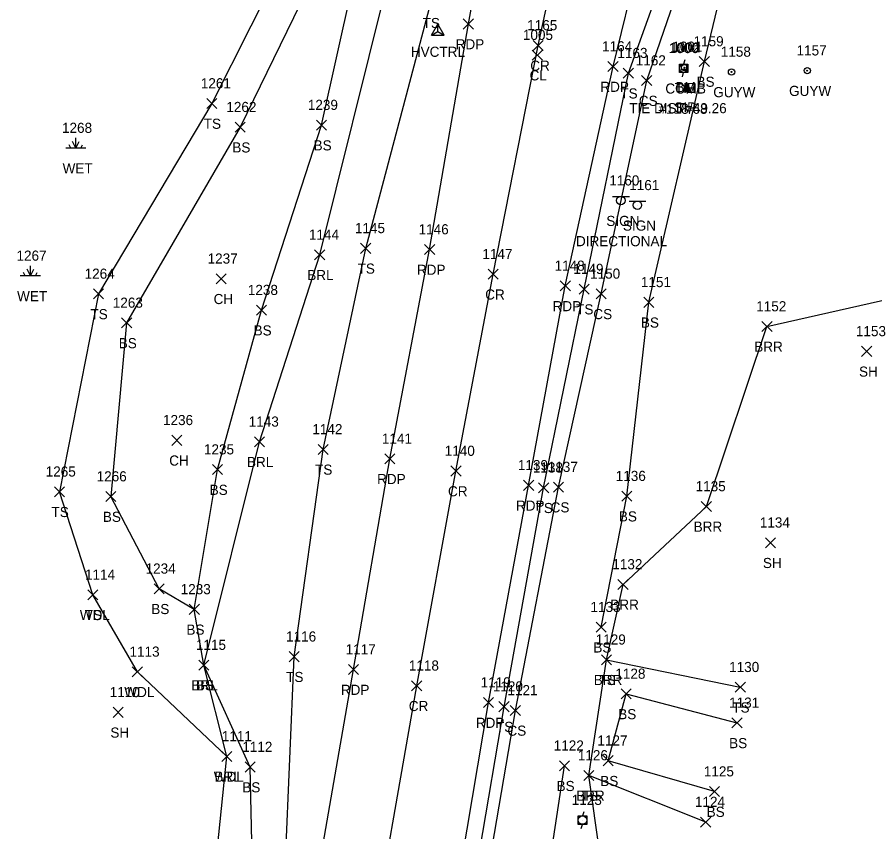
# Model space of a CAD drawing. Extents: x 1654425 to 1656893, y 667839 to 678429.
# Drawn here: x 1654474.9 to 1654644.4, y 668104.4 to 668265.4 of the extents above; entities that cross this region are included whole.
import ezdxf

# ---------------------------------------------------------------- set-up
doc = ezdxf.new("R2010")
doc.units = 0
for name, color, linetype in [('A_A', 7, 'Continuous'), ('A_I', 7, 'Continuous'), ('A_TIC', 7, 'Continuous'), ('C_A', 7, 'Continuous'), ('C_C', 7, 'Continuous'), ('C_I', 7, 'Continuous'), ('CBP', 7, 'Continuous'), ('CPBM', 7, 'Continuous'), ('CPSM', 7, 'Continuous'), ('L_A', 7, 'Continuous'), ('L_I', 7, 'Continuous'), ('L_TIC', 7, 'Continuous'), ('LABL', 7, 'Continuous'), ('LAWA', 7, 'Continuous'), ('LELB', 7, 'Continuous'), ('LWET', 7, 'Continuous'), ('P_A', 7, 'Continuous'), ('P_I', 7, 'Continuous'), ('P_TIC', 7, 'Continuous'), ('PET', 7, 'Continuous'), ('PRC', 7, 'Continuous'), ('S_A', 7, 'Continuous'), ('S_C', 7, 'Continuous'), ('S_I', 7, 'Continuous'), ('SSGN', 7, 'Continuous'), ('U_A', 7, 'Continuous'), ('U_C', 7, 'Continuous'), ('U_I', 7, 'Continuous'), ('UP', 7, 'Continuous'), ('UPGW', 7, 'Continuous')]:
    doc.layers.add(name, color=color, linetype=linetype)

msp = doc.modelspace()

# ---------------------------------------------------------------- linework, layer by layer
at = {"layer": 'A_TIC'}
for points in [[(1654576.68, 668256.91), (1654578.68, 668258.91)], [(1654578.68, 668256.91), (1654576.68, 668258.91)]]:
    msp.add_lwpolyline(points, dxfattribs=at)
at = {"layer": 'CBP'}
for radius in [0.625, 0.0833]:
    msp.add_circle((1654606.76, 668255.43), radius, dxfattribs=at)
at = {"layer": 'CPBM'}
for p, q in [((1654606.14, 668255.08), (1654606.14, 668256.08)), ((1654606.14, 668256.08), (1654607.14, 668256.08)), ((1654607.14, 668255.08), (1654606.14, 668255.08)), ((1654606.64, 668255.58), (1654606.64, 668255.58)), ((1654606.64, 668255.58), (1654606.64, 668255.58)), ((1654607.14, 668256.08), (1654607.14, 668255.08))]:
    msp.add_line(p, q, dxfattribs=at)
at = {"layer": 'CPSM'}
for p, q in [((1654556.76, 668261.85), (1654558.01, 668264.01)), ((1654559.26, 668261.85), (1654558.01, 668264.01)), ((1654558.01, 668262.57), (1654558.01, 668264.01)), ((1654556.76, 668261.85), (1654558.01, 668262.57)), ((1654556.76, 668261.85), (1654559.26, 668261.85)), ((1654558.01, 668262.57), (1654558.01, 668262.57)), ((1654558.01, 668262.57), (1654559.26, 668261.85))]:
    msp.add_line(p, q, dxfattribs=at)
at = {"layer": 'L_TIC'}
for points in [[(1654609.68, 668255.65), (1654611.68, 668257.65)], [(1654611.68, 668255.65), (1654609.68, 668257.65)], [(1654594.67, 668253.34), (1654596.67, 668255.34)], [(1654596.67, 668253.34), (1654594.67, 668255.34)], [(1654598.29, 668251.88), (1654600.29, 668253.88)], [(1654600.29, 668251.88), (1654598.29, 668253.88)], [(1654512.38, 668247.35), (1654514.38, 668249.35)], [(1654514.38, 668247.35), (1654512.38, 668249.35)], [(1654517.99, 668242.67), (1654519.99, 668244.67)], [(1654519.99, 668242.67), (1654517.99, 668244.67)], [(1654534.05, 668243.08), (1654536.05, 668245.08)], [(1654536.05, 668243.08), (1654534.05, 668245.08)], [(1654533.69, 668217.45), (1654535.69, 668219.45)], [(1654535.69, 668217.45), (1654533.69, 668219.45)], [(1654542.78, 668218.73), (1654544.78, 668220.73)], [(1654544.78, 668218.73), (1654542.78, 668220.73)], [(1654514.25, 668212.72), (1654516.25, 668214.72)], [(1654516.25, 668212.72), (1654514.25, 668214.72)], [(1654585.94, 668210.68), (1654587.94, 668212.68)], [(1654587.94, 668210.68), (1654585.94, 668212.68)], [(1654490, 668209.73), (1654492, 668211.73)], [(1654492, 668209.73), (1654490, 668211.73)], [(1654589.31, 668209.74), (1654591.31, 668211.74)], [(1654591.31, 668209.74), (1654589.31, 668211.74)], [(1654598.7, 668208.07), (1654600.7, 668210.07)], [(1654600.7, 668208.07), (1654598.7, 668210.07)], [(1654522.2, 668206.52), (1654524.2, 668208.52)], [(1654524.2, 668206.52), (1654522.2, 668208.52)], [(1654495.56, 668204), (1654497.56, 668206)], [(1654497.56, 668204), (1654495.56, 668206)], [(1654622.05, 668203.29), (1654624.05, 668205.29)], [(1654624.05, 668203.29), (1654622.05, 668205.29)], [(1654641.74, 668198.38), (1654643.74, 668200.38)], [(1654643.74, 668198.38), (1654641.74, 668200.38)], [(1654505.49, 668180.81), (1654507.49, 668182.81)], [(1654507.49, 668180.81), (1654505.49, 668182.81)], [(1654521.79, 668180.51), (1654523.79, 668182.51)], [(1654523.79, 668180.51), (1654521.79, 668182.51)], [(1654534.37, 668179.01), (1654536.37, 668181.01)], [(1654536.37, 668179.01), (1654534.37, 668181.01)], [(1654513.52, 668175.02), (1654515.52, 668177.02)], [(1654515.52, 668175.02), (1654513.52, 668177.02)], [(1654577.93, 668171.43), (1654579.93, 668173.43)], [(1654579.93, 668171.43), (1654577.93, 668173.43)], [(1654580.87, 668171.56), (1654582.87, 668173.56)], [(1654582.87, 668171.56), (1654580.87, 668173.56)], [(1654482.31, 668170.64), (1654484.31, 668172.64)], [(1654484.31, 668170.64), (1654482.31, 668172.64)], [(1654482.31, 668170.64), (1654484.31, 668172.64)], [(1654484.31, 668170.64), (1654482.31, 668172.64)], [(1654492.42, 668169.69), (1654494.42, 668171.69)], [(1654494.42, 668169.69), (1654492.42, 668171.69)], [(1654492.42, 668169.69), (1654494.42, 668171.69)], [(1654494.42, 668169.69), (1654492.42, 668171.69)], [(1654594.35, 668169.77), (1654596.35, 668171.77)], [(1654596.35, 668169.77), (1654594.35, 668171.77)], [(1654610.07, 668167.74), (1654612.07, 668169.74)], [(1654612.07, 668167.74), (1654610.07, 668169.74)], [(1654622.76, 668160.57), (1654624.76, 668162.57)], [(1654624.76, 668160.57), (1654622.76, 668162.57)], [(1654501.99, 668151.47), (1654503.99, 668153.47)], [(1654503.99, 668151.47), (1654501.99, 668153.47)], [(1654593.61, 668152.33), (1654595.61, 668154.33)], [(1654595.61, 668152.33), (1654593.61, 668154.33)], [(1654488.89, 668150.28), (1654490.89, 668152.28)], [(1654490.89, 668150.28), (1654488.89, 668152.28)], [(1654488.89, 668150.28), (1654490.89, 668152.28)], [(1654490.89, 668150.28), (1654488.89, 668152.28)], [(1654508.93, 668147.4), (1654510.93, 668149.4)], [(1654510.93, 668147.4), (1654508.93, 668149.4)], [(1654508.93, 668147.4), (1654510.93, 668149.4)], [(1654510.93, 668147.4), (1654508.93, 668149.4)], [(1654589.31, 668143.88), (1654591.31, 668145.88)], [(1654591.31, 668143.88), (1654589.31, 668145.88)], [(1654528.66, 668138.05), (1654530.66, 668140.05)], [(1654530.66, 668138.05), (1654528.66, 668140.05)], [(1654510.8, 668136.4), (1654512.8, 668138.4)], [(1654512.8, 668136.4), (1654510.8, 668138.4)], [(1654510.8, 668136.4), (1654512.8, 668138.4)], [(1654512.8, 668136.4), (1654510.8, 668138.4)], [(1654590.34, 668137.45), (1654592.34, 668139.45)], [(1654592.34, 668137.45), (1654590.34, 668139.45)], [(1654590.34, 668137.45), (1654592.34, 668139.45)], [(1654592.34, 668137.45), (1654590.34, 668139.45)], [(1654497.68, 668135.06), (1654499.68, 668137.06)], [(1654499.68, 668135.06), (1654497.68, 668137.06)], [(1654594.22, 668130.7), (1654596.22, 668132.7)], [(1654596.22, 668130.7), (1654594.22, 668132.7)], [(1654616.78, 668132.02), (1654618.78, 668134.02)], [(1654618.78, 668132.02), (1654616.78, 668134.02)], [(1654570.11, 668128.18), (1654572.11, 668130.18)], [(1654572.11, 668128.18), (1654570.11, 668130.18)], [(1654572.34, 668127.44), (1654574.34, 668129.44)], [(1654574.34, 668127.44), (1654572.34, 668129.44)], [(1654493.87, 668127.06), (1654495.87, 668129.06)], [(1654495.87, 668127.06), (1654493.87, 668129.06)], [(1654616.12, 668124.98), (1654618.12, 668126.98)], [(1654618.12, 668124.98), (1654616.12, 668126.98)], [(1654515.35, 668118.35), (1654517.35, 668120.35)], [(1654517.35, 668118.35), (1654515.35, 668120.35)], [(1654515.35, 668118.35), (1654517.35, 668120.35)], [(1654517.35, 668118.35), (1654515.35, 668120.35)], [(1654590.68, 668117.5), (1654592.68, 668119.5)], [(1654592.68, 668117.5), (1654590.68, 668119.5)], [(1654519.96, 668116.25), (1654521.96, 668118.25)], [(1654521.96, 668116.25), (1654519.96, 668118.25)], [(1654582.04, 668116.51), (1654584.04, 668118.51)], [(1654584.04, 668116.51), (1654582.04, 668118.51)], [(1654586.86, 668114.59), (1654588.86, 668116.59)], [(1654588.86, 668114.59), (1654586.86, 668116.59)], [(1654586.86, 668114.59), (1654588.86, 668116.59)], [(1654588.86, 668114.59), (1654586.86, 668116.59)], [(1654611.69, 668111.4), (1654613.69, 668113.4)], [(1654613.69, 668111.4), (1654611.69, 668113.4)], [(1654609.94, 668105.38), (1654611.94, 668107.38)], [(1654611.94, 668105.38), (1654609.94, 668107.38)]]:
    msp.add_lwpolyline(points, dxfattribs=at)
at = {"layer": 'LABL'}
for points in [[(1654516.35, 668119.35), (1654511.8, 668137.4), (1654522.79, 668181.51), (1654534.69, 668218.45), (1654547.69, 668270.66), (1654546.04, 668295.57)], [(1654605, 668046.16), (1654594.45, 668068.9), (1654587.86, 668115.59), (1654591.34, 668138.45), (1654594.61, 668153.33), (1654611.07, 668168.74), (1654623.05, 668204.29), (1654669.38, 668214.79), (1654714.24, 668210.79)]]:
    msp.add_lwpolyline(points, dxfattribs=at)
at = {"layer": 'LAWA'}
msp.add_lwpolyline([(1654487.86, 667850.24), (1654494.84, 667897.34), (1654500.67, 667940.77), (1654505.51, 667978.89), (1654509.61, 668019.56), (1654510.39, 668046.1), (1654508.8, 668074.55), (1654512.45, 668081.46), (1654516.35, 668119.35), (1654498.68, 668136.06), (1654489.89, 668151.28)], dxfattribs=at)
at = {"layer": 'LELB'}
for points in [[(1654562.65, 668358.71), (1654556.85, 668347.4), (1654550.86, 668336.48), (1654541.59, 668302.56), (1654534.79, 668276.13), (1654518.99, 668243.67), (1654496.56, 668205), (1654493.42, 668170.69)], [(1654495.43, 667849.08), (1654500.81, 667895.96), (1654505.52, 667939.5), (1654510.36, 667978.52), (1654516.04, 668017.45), (1654520.13, 668047.02), (1654521.8, 668078.81), (1654520.96, 668117.25), (1654511.8, 668137.4), (1654509.93, 668148.4), (1654514.52, 668176.02), (1654523.2, 668207.52), (1654535.05, 668244.08), (1654541.09, 668271.34), (1654546.04, 668295.57), (1654553.44, 668325.52), (1654559.28, 668346.56), (1654565.49, 668358.45)], [(1654497.51, 667848.84), (1654501.99, 667895.85), (1654506.8, 667938.86), (1654511.52, 667978.38), (1654518.04, 668017.75), (1654522.23, 668046.7), (1654527.11, 668078.6), (1654529.66, 668139.05), (1654535.37, 668180.01), (1654543.78, 668219.73), (1654556.62, 668268.25), (1654562.63, 668297.63), (1654565.24, 668311.03), (1654570.38, 668336.59), (1654576.33, 668345.51)], [(1654532.88, 667846.44), (1654536.81, 667893.31), (1654541.08, 667931.05), (1654546.18, 667972.49), (1654551.95, 668011.91), (1654556.54, 668041.44), (1654561.5, 668072.5), (1654571.11, 668129.18), (1654578.93, 668172.43), (1654586.94, 668211.68), (1654595.67, 668254.34), (1654607.41, 668286.92), (1654610.93, 668292.61), (1654617.54, 668318.12), (1654616.79, 668336.32)], [(1654590.31, 668144.88), (1654595.35, 668170.77), (1654599.7, 668209.07), (1654610.68, 668256.65), (1654619.6, 668293.68), (1654624.42, 668321.72), (1654620.94, 668333.17)], [(1654537.5, 668307.15), (1654528.81, 668278.95), (1654513.38, 668248.35), (1654491, 668210.73), (1654483.31, 668171.64)], [(1654543.76, 667929.96), (1654549.41, 667971.89), (1654554.38, 668011.7), (1654559.28, 668041.03), (1654563.69, 668071.7), (1654573.34, 668128.44), (1654581.87, 668172.56), (1654590.31, 668210.74), (1654599.29, 668252.88), (1654609.98, 668283.91), (1654610.93, 668292.61)], [(1654489.89, 668151.28), (1654483.31, 668171.64)], [(1654509.93, 668148.4), (1654502.99, 668152.47), (1654493.42, 668170.69)], [(1654591.34, 668138.45), (1654617.78, 668133.02)], [(1654612.69, 668112.4), (1654591.68, 668118.5), (1654595.22, 668131.7), (1654617.12, 668125.98)], [(1654538.26, 667846.15), (1654542.65, 667893.12), (1654546.8, 667929.18), (1654553.5, 667971.67), (1654558.51, 668011.64), (1654562.47, 668041.03), (1654569.65, 668073.66), (1654578.54, 668087.47), (1654583.04, 668117.51)], [(1654610.94, 668106.38), (1654587.86, 668115.59)]]:
    msp.add_lwpolyline(points, dxfattribs=at)
at = {"layer": 'LWET'}
for p, q in [((1654486.53, 668239.54), (1654486.53, 668241.54)), ((1654488.53, 668239.54), (1654484.53, 668239.54)), ((1654485.53, 668239.54), (1654485.2, 668240.21)), ((1654486.53, 668239.54), (1654485.86, 668240.87)), ((1654486.53, 668239.54), (1654487.2, 668240.87)), ((1654487.53, 668239.54), (1654487.86, 668240.21)), ((1654477.54, 668214.29), (1654477.54, 668216.29)), ((1654479.54, 668214.29), (1654475.54, 668214.29)), ((1654476.54, 668214.29), (1654476.21, 668214.96)), ((1654477.54, 668214.29), (1654476.88, 668215.62)), ((1654477.54, 668214.29), (1654478.21, 668215.62)), ((1654478.54, 668214.29), (1654478.88, 668214.96))]:
    msp.add_line(p, q, dxfattribs=at)
at = {"layer": 'P_TIC'}
for points in [[(1654563.06, 668263.06), (1654565.06, 668265.06)], [(1654565.06, 668263.06), (1654563.06, 668265.06)], [(1654576.86, 668258.83), (1654578.86, 668260.83)], [(1654578.86, 668258.83), (1654576.86, 668260.83)], [(1654591.64, 668254.65), (1654593.64, 668256.65)], [(1654593.64, 668254.65), (1654591.64, 668256.65)], [(1654555.41, 668218.5), (1654557.41, 668220.5)], [(1654557.41, 668218.5), (1654555.41, 668220.5)], [(1654567.95, 668213.62), (1654569.95, 668215.62)], [(1654569.95, 668213.62), (1654567.95, 668215.62)], [(1654582.21, 668211.31), (1654584.21, 668213.31)], [(1654584.21, 668211.31), (1654582.21, 668213.31)], [(1654547.54, 668177.15), (1654549.54, 668179.15)], [(1654549.54, 668177.15), (1654547.54, 668179.15)], [(1654560.61, 668174.74), (1654562.61, 668176.74)], [(1654562.61, 668174.74), (1654560.61, 668176.74)], [(1654574.97, 668171.91), (1654576.97, 668173.91)], [(1654576.97, 668171.91), (1654574.97, 668173.91)], [(1654540.38, 668135.51), (1654542.38, 668137.51)], [(1654542.38, 668135.51), (1654540.38, 668137.51)], [(1654552.86, 668132.31), (1654554.86, 668134.31)], [(1654554.86, 668132.31), (1654552.86, 668134.31)], [(1654567.05, 668128.99), (1654569.05, 668130.99)], [(1654569.05, 668128.99), (1654567.05, 668130.99)]]:
    msp.add_lwpolyline(points, dxfattribs=at)
at = {"layer": 'PET'}
for points in [[(1654500.93, 667848.14), (1654504.78, 667896.02), (1654509.67, 667937.82), (1654515.37, 667977.68), (1654521.39, 668016.85), (1654525.99, 668046.3), (1654531.26, 668078.24), (1654541.38, 668136.51), (1654548.54, 668178.15), (1654556.41, 668219.5), (1654564.06, 668264.06), (1654572.07, 668308.08), (1654579.91, 668345.23), (1654595.42, 668341.51), (1654611.88, 668337.75)], [(1654528.99, 667846.47), (1654531.96, 667893.38), (1654537.26, 667931.97), (1654542.41, 667973.09), (1654548.22, 668012.23), (1654553.01, 668041.79), (1654558.55, 668073.69), (1654568.05, 668129.99), (1654575.97, 668172.91), (1654583.21, 668212.31), (1654592.64, 668255.65), (1654604.22, 668302.74), (1654611.88, 668337.75)]]:
    msp.add_lwpolyline(points, dxfattribs=at)
at = {"layer": 'PRC'}
msp.add_lwpolyline([(1654514.39, 667847.42), (1654517.73, 667895.01), (1654522.68, 667935.26), (1654527.79, 667975.85), (1654533.53, 668014.87), (1654538.36, 668044.09), (1654543.94, 668076.54), (1654553.86, 668133.31), (1654561.61, 668175.74), (1654568.95, 668214.62), (1654577.86, 668259.83), (1654587.68, 668305.21), (1654595.42, 668341.51)], dxfattribs=at)
at = {"layer": 'SSGN'}
for p, q in [((1654592.52, 668230), (1654595.86, 668230)), ((1654594.17, 668229.17), (1654594.17, 668229.17)), ((1654595.81, 668229.08), (1654599.14, 668229.08)), ((1654597.45, 668228.25), (1654597.45, 668228.25))]:
    msp.add_line(p, q, dxfattribs=at)
for centre in [(1654594.17, 668229.17), (1654597.45, 668228.25)]:
    msp.add_circle(centre, 0.833, dxfattribs=at)
at = {"layer": 'UP'}
for p, q in [((1654606.84, 668256.98), (1654606.59, 668256.15)), ((1654605.75, 668254.48), (1654605.75, 668256.15)), ((1654605.75, 668256.15), (1654607.42, 668256.15)), ((1654606.59, 668255.31), (1654606.59, 668255.31)), ((1654607.42, 668256.15), (1654607.42, 668254.48)), ((1654607.42, 668254.48), (1654605.75, 668254.48)), ((1654606.34, 668253.65), (1654606.59, 668254.48)), ((1654585.78, 668105.93), (1654585.78, 668107.6)), ((1654585.78, 668107.6), (1654587.44, 668107.6)), ((1654586.86, 668108.43), (1654586.61, 668107.6)), ((1654587.44, 668107.6), (1654587.44, 668105.93)), ((1654587.44, 668105.93), (1654585.78, 668105.93)), ((1654586.36, 668105.1), (1654586.61, 668105.93)), ((1654586.61, 668106.77), (1654586.61, 668106.77))]:
    msp.add_line(p, q, dxfattribs=at)
for centre in [(1654606.59, 668255.31), (1654586.61, 668106.77)]:
    msp.add_circle(centre, 0.833, dxfattribs=at)
at = {"layer": 'UPGW'}
for centre, radius in [((1654616.05, 668254.59), 0.625), ((1654631.01, 668254.84), 0.625), ((1654631.01, 668254.84), 0.0833), ((1654616.05, 668254.59), 0.0833)]:
    msp.add_circle(centre, radius, dxfattribs=at)

# ---------------------------------------------------------------- texts
at = {"layer": 'A_A'}
msp.add_text('CL', height=2, dxfattribs=at).set_placement((1654576.16, 668252.91))
at = {"layer": 'A_I'}
msp.add_text('1005', height=2, dxfattribs=at).set_placement((1654574.83, 668260.91))
at = {"layer": 'C_A'}
for s, p in [('HVCTRL', (1654552.7, 668257.57)), ('TIE', (1654604.84, 668250.43)), ('BM', (1654604.96, 668250.58))]:
    msp.add_text(s, height=2, dxfattribs=at).set_placement(p)
at = {"layer": 'C_C'}
for s, p in [('TIE DIST=49.26', (1654595.84, 668246.43)), ('SIP', (1654604.74, 668246.58))]:
    msp.add_text(s, height=2, dxfattribs=at).set_placement(p)
at = {"layer": 'C_I'}
for s, p in [('1002', (1654603.91, 668258.43)), ('1001', (1654604.36, 668258.58))]:
    msp.add_text(s, height=2, dxfattribs=at).set_placement(p)
at = {"layer": 'L_A'}
for s, p in [('TS', (1654555.03, 668263.25)), ('BS', (1654609.12, 668251.65)), ('TS', (1654594.08, 668249.34)), ('CS', (1654597.73, 668247.88)), ('TS', (1654511.79, 668243.35)), ('BS', (1654517.44, 668238.67)), ('BS', (1654533.49, 668239.08)), ('WET', (1654483.91, 668234.54)), ('TS', (1654542.18, 668214.73)), ('BRL', (1654532.24, 668213.45)), ('WET', (1654474.92, 668209.29)), ('CH', (1654513.74, 668208.72)), ('TS', (1654489.41, 668205.73)), ('TS', (1654585.35, 668206.68)), ('CS', (1654588.75, 668205.74)), ('BS', (1654598.14, 668204.07)), ('BS', (1654521.64, 668202.52)), ('BS', (1654495, 668200)), ('BRR', (1654620.53, 668199.29)), ('SH', (1654641.23, 668194.38)), ('CH', (1654504.97, 668176.81)), ('BRL', (1654520.33, 668176.51)), ('TS', (1654533.78, 668175.01)), ('BS', (1654512.96, 668171.02)), ('TS', (1654481.72, 668166.64)), ('TS', (1654481.72, 668166.64)), ('TS', (1654577.34, 668167.43)), ('CS', (1654580.31, 668167.56)), ('BS', (1654491.86, 668165.69)), ('BS', (1654491.86, 668165.69)), ('BS', (1654593.79, 668165.77)), ('BRR', (1654608.56, 668163.74)), ('SH', (1654622.24, 668156.57)), ('BRR', (1654592.1, 668148.33)), ('WDL', (1654487.31, 668146.28)), ('TS', (1654488.3, 668146.28)), ('BS', (1654501.43, 668147.47)), ('BS', (1654508.37, 668143.4)), ('BS', (1654508.37, 668143.4)), ('BS', (1654588.75, 668139.88)), ('BRL', (1654509.34, 668132.4)), ('BS', (1654510.24, 668132.4)), ('TS', (1654528.07, 668134.05)), ('BRR', (1654588.83, 668133.45)), ('TS', (1654589.75, 668133.45)), ('WDL', (1654496.1, 668131.06)), ('TS', (1654616.19, 668128.02)), ('BS', (1654593.66, 668126.7)), ('TS', (1654569.52, 668124.18)), ('SH', (1654493.35, 668123.06)), ('CS', (1654571.78, 668123.44)), ('BS', (1654615.57, 668120.98)), ('WDL', (1654513.77, 668114.35)), ('BRL', (1654513.9, 668114.35)), ('BS', (1654519.4, 668112.25)), ('BS', (1654581.48, 668112.51)), ('BS', (1654590.12, 668113.5)), ('BRR', (1654585.35, 668110.59)), ('TS', (1654586.27, 668110.59)), ('BS', (1654611.13, 668107.4))]:
    msp.add_text(s, height=2, dxfattribs=at).set_placement(p)
at = {"layer": 'L_I'}
for s, p in [('1159', (1654608.54, 668259.65)), ('1163', (1654593.5, 668257.34)), ('1162', (1654597.12, 668255.88)), ('1261', (1654511.21, 668251.35)), ('1262', (1654516.25, 668246.67)), ('1239', (1654532.35, 668247.08)), ('1268', (1654483.79, 668242.54)), ('1145', (1654541.65, 668222.73)), ('1144', (1654532.57, 668221.45)), ('1267', (1654474.8, 668217.29)), ('1237', (1654512.55, 668216.72)), ('1264', (1654488.26, 668213.73)), ('1149', (1654584.81, 668214.68)), ('1150', (1654588.1, 668213.74)), ('1151', (1654598.14, 668212.07)), ('1238', (1654520.5, 668210.52)), ('1263', (1654493.82, 668208)), ('1152', (1654620.92, 668207.29)), ('1153', (1654640.61, 668202.38)), ('1236', (1654503.74, 668184.81)), ('1143', (1654520.67, 668184.51)), ('1142', (1654533.24, 668183.01)), ('1235', (1654511.83, 668179.02)), ('1138', (1654576.8, 668175.43)), ('1137', (1654579.74, 668175.56)), ('1265', (1654480.57, 668174.64)), ('1265', (1654480.57, 668174.64)), ('1266', (1654490.63, 668173.69)), ('1266', (1654490.63, 668173.69)), ('1136', (1654593.17, 668173.77)), ('1135', (1654608.95, 668171.74)), ('1134', (1654621.63, 668164.57)), ('1132', (1654592.49, 668156.33)), ('1234', (1654500.3, 668155.47)), ('1114', (1654488.33, 668154.28)), ('1114', (1654488.33, 668154.28)), ('1233', (1654507.23, 668151.4)), ('1233', (1654507.23, 668151.4)), ('1133', (1654588.18, 668147.88)), ('1116', (1654528.05, 668142.05)), ('1129', (1654589.21, 668141.45)), ('1129', (1654589.21, 668141.45)), ('1115', (1654510.24, 668140.4)), ('1115', (1654510.24, 668140.4)), ('1113', (1654497.12, 668139.06)), ('1130', (1654615.57, 668136.02)), ('1128', (1654593.09, 668134.7)), ('1110', (1654493.22, 668131.06)), ('1120', (1654568.89, 668132.18)), ('1121', (1654571.78, 668131.44)), ('1131', (1654615.57, 668128.98)), ('1111', (1654515.36, 668122.35)), ('1111', (1654515.36, 668122.35)), ('1122', (1654580.92, 668120.51)), ('1127', (1654589.55, 668121.5)), ('1112', (1654519.4, 668120.25)), ('1126', (1654585.68, 668118.59)), ('1126', (1654585.68, 668118.59)), ('1125', (1654610.57, 668115.4)), ('1124', (1654608.81, 668109.38))]:
    msp.add_text(s, height=2, dxfattribs=at).set_placement(p)
at = {"layer": 'P_A'}
for s, p in [('RDP', (1654561.55, 668259.06)), ('CR', (1654576.29, 668254.83)), ('RDP', (1654590.13, 668250.65)), ('RDP', (1654553.9, 668214.5)), ('CR', (1654567.39, 668209.62)), ('RDP', (1654580.7, 668207.31)), ('RDP', (1654546.03, 668173.15)), ('CR', (1654560.04, 668170.74)), ('RDP', (1654573.46, 668167.91)), ('RDP', (1654538.87, 668131.51)), ('CR', (1654552.29, 668128.31)), ('RDP', (1654565.53, 668124.99))]:
    msp.add_text(s, height=2, dxfattribs=at).set_placement(p)
at = {"layer": 'P_I'}
for s, p in [('1165', (1654575.68, 668262.83)), ('1164', (1654590.47, 668258.65)), ('1146', (1654554.23, 668222.5)), ('1147', (1654566.83, 668217.62)), ('1148', (1654581.09, 668215.31)), ('1141', (1654546.98, 668181.15)), ('1140', (1654559.39, 668178.74)), ('1139', (1654573.84, 668175.91)), ('1117', (1654539.82, 668139.51)), ('1118', (1654552.3, 668136.31)), ('1119', (1654566.48, 668132.99))]:
    msp.add_text(s, height=2, dxfattribs=at).set_placement(p)
at = {"layer": 'S_A'}
for p in [(1654591.31, 668224.15), (1654594.59, 668223.23)]:
    msp.add_text('SIGN', height=2, dxfattribs=at).set_placement(p)
at = {"layer": 'S_C'}
msp.add_text('DIRECTIONAL', height=2, dxfattribs=at).set_placement((1654585.32, 668220.15))
at = {"layer": 'S_I'}
for s, p in [('1160', (1654591.89, 668232.15)), ('1161', (1654595.83, 668231.23))]:
    msp.add_text(s, height=2, dxfattribs=at).set_placement(p)
at = {"layer": 'U_A'}
for s, p in [('COMB', (1654602.97, 668250.31)), ('GUYW', (1654612.44, 668249.59)), ('GUYW', (1654627.41, 668249.84))]:
    msp.add_text(s, height=2, dxfattribs=at).set_placement(p)
at = {"layer": 'U_C'}
msp.add_text('#118/68', height=2, dxfattribs=at).set_placement((1654601.64, 668246.31))
at = {"layer": 'U_I'}
for s, p in [('1000', (1654603.65, 668258.31)), ('1157', (1654628.89, 668257.84)), ('1158', (1654613.92, 668257.59)), ('1123', (1654584.48, 668109.77))]:
    msp.add_text(s, height=2, dxfattribs=at).set_placement(p)

doc.saveas('drawing.dxf')
